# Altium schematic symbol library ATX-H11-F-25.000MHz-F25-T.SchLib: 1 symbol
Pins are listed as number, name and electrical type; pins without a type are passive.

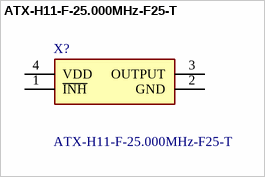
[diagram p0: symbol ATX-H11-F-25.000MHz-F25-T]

## ATX-H11-F-25.000MHz-F25-T
designator X?
XTAL OSC TCXO 25MHz CMOS; Manufacturer_Name: ABRACON; Geometry.Height: 1.2mm
footprint ATXH11F25000MHzF25T
pins: 1 ~{INH}, 2 GND, 3 OUTPUT, 4 VDD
